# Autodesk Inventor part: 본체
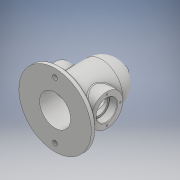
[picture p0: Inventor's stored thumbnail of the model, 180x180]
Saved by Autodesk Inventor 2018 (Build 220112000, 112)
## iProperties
Created: 2019-11
Part Number: 본체
Material: Generic
Document SubType Name: Modeling
Designer: Administrator
Density: 1 g/cm^3
Appearance: Default
Author: Administrator
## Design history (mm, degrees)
sketch "스케치1"
  geometry: C1 r 70 at (0, 0); 1 further point
  constraints: 1 centre point, 1 coincident
  dimensions: "d0" = 140 diameter of C1
extrude "돌출1" new body sketch "스케치1" distance "d1" = 10; taper "d2" = 0 deg
sketch "스케치2"
  geometry: C1 r 40 at (0, 0); 1 further point
  constraints: 1 centre point, 1 coincident
  dimensions: "d3" = 80 diameter of C1
extrude "돌출2" join sketch "스케치2" distance "d4" = 80; taper "d5" = 0 deg
sketch "스케치4"
  geometry: L1 (90, -40)-(90, 40) reference; L2 (90, 0)-(130, 0); L3 (90, 40)-(90, 0); A1 r 40 centre (90, 0) between (130, 0) and (90, 40); 1 further point
  constraints: 5 end point, 2 point on circle, 1 centre point, 1 coincident, 1 collinear, 1 horizontal, 1 midpoint, 1 point on line
revolve "회전1" sketch "스케치4" stored, may be unused: angle "d7" = 90 deg
chamfer "모따기1" distance "d8" = 3; stored, may be unused: second distance "d9" = 2, angle "d10" = 45 deg
sketch "스케치5"
  geometry: C1 r 31 at (50, 0); 1 further point
  constraints: 1 centre point
extrude "돌출3" join sketch "스케치5" stored distance "d13" = 100; taper "d14" = 0 deg
sketch "스케치6"
  geometry: C1 r 20 at (0, 0); 1 further point
  constraints: 1 centre point
  dimensions: "d15" = 40 diameter of C1
extrude "돌출4" cut sketch "스케치6" distance "d16" = 15; taper "d17" = 0 deg
sketch "스케치7"
  geometry: C1 r 16.5 at (0, 0); 1 further point
  constraints: 1 centre point
  dimensions: "d18" = 33 diameter of C1
extrude "돌출5" cut sketch "스케치7" extent not by distance; stored distance "d19" = 15; taper "d20" = 0 deg
chamfer "모따기2" distance "d21" = 1; stored, may be unused: second distance "d22" = 2, angle "d23" = 45 deg
fillet "모깎기1" dims "d24" = 0.3
sketch "스케치8"
  geometry: 5 further points
hole "구멍1" sketch "스케치8" at (0, 26), (-26, 0), (0, -26), (26, 0) diameter "d26" = 3.242; stored, may be unused: countersink angle "d30" = 90 deg, drill point angle "d32" = 118 deg; dims "d27" = 8, "d28" = 4, "d29" = 2, "d31" = 10
sketch "스케치9"
  geometry: C1 r 30 at (0, 0); 1 further point
  constraints: 1 centre point, 1 coincident
  dimensions: "d33" = 60 diameter of C1
extrude "돌출6" cut sketch "스케치9" distance "d34" = 90; taper "d35" = 0 deg
sketch "스케치11"
  geometry: L1 (90, -40)-(90, 40) reference; L2 (90, 0)-(120, 0); L3 (90, 0)-(90, 30); A1 r 30 centre (90, 0) between (120, 0) and (90, 30); 1 further point
  constraints: 4 end point, 2 point on circle, 1 centre point, 1 collinear, 1 midpoint, 1 point on line
revolve "회전2" sketch "스케치11" stored, may be unused: angle "d39" = 90 deg
sketch "스케치12"
  geometry: C1 r 4.5 at (0, -55); C2 r 4.5 at (0, 55); 1 further point
  constraints: 2 centre point
  dimensions: "d41" = 9 diameter of C1; "d42" = 9 diameter of C2
extrude "돌출7" cut sketch "스케치12" extent not by distance; stored distance "d43" = 90; taper "d44" = 0 deg
node "작업 평면2"
  node "작업 평면1"
sketch "스케치13"
  geometry: C1 r 7.5 at (0, 0); 1 further point
  constraints: 1 centre point, 1 coincident
  dimensions: "d46" = 15 diameter of C1
extrude "돌출8" join sketch "스케치13" distance "d47" = 7; taper "d48" = 0 deg
sketch "스케치14"
  geometry: 2 further points
  constraints: 1 coincident
hole "구멍2" sketch "스케치14" at (0, 0) diameter "d49" = 5.188; stored, may be unused: countersink angle "d53" = 90 deg, drill point angle "d55" = 118 deg; dims "d50" = 12, "d51" = 4, "d52" = 2, "d54" = 16
fillet "모깎기2" dims "d56" = 3
fillet "모깎기3" dims "d57" = 3
node "작업 평면3"
sketch "스케치15"
  geometry: L1 (-70, -10)-(70, -10) reference; 3 further points
  constraints: 1 midpoint, 1 vertical alignment, 1 other
feature "엠보싱1" sketch "스케치15" dims "d59" = 0.5, "d60" = 0
node "솔리드1"
mirror "미러1"
mirror "미러2"
other parameters: "d45" = -2
